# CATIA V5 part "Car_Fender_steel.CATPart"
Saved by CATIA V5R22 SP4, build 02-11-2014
Part number: Car_Fender
Material "ｽﾁｰﾙ": density 7860 kg/m3, Young's modulus 2e+11 Pa, Poisson ratio 0.266, thermal expansion 1.17e-05 1/K
Bounding box of the stored display mesh (mm): x -800 to 0, y -40 to 122.298, z 0 to 580
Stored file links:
  \\172.16.16.24\714_東北電子専門学校\2014年度\02_実施プロセス\catia_model_data\CAE_data\Car_modify\Car_Fender_steel.CATPart
  C:\Program Files\Dassault Systemes\B22\win_b64\startup\materials\red_env_512x512.jpg
  C:\Program Files\Dassault Systemes\B22\win_b64\startup\materials\yellow_env_512x512.jpg

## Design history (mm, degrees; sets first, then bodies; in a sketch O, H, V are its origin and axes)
Set1
  Plane1: type Offset, RefPlane yz-plane, Offset 400, reversed
  Plane2 "平面.2": type Offset, RefPlane Plane1, Offset 400, reversed
Body1 (main body)
  Body2
    Sketch1 on yz-plane, origin (0, 0, 0), H (0, 1, 0), V (0, 0, 1)
      point P1 (40.1932, 0)
      point P2 (100, 50)
      line L1 (100, 50) -> (100, 0)
      point P3 (100, 0)
      line L2 (100, 0) -> (0, 0)
      line L3 (0, 0) -> (0, 450)
      line L4 (0, 450) -> (10, 450)
      point P5 (10, 450)
      spline S1 through (10, 450) (100, 50)
      point P6 (10, 450)
      point P7 (100, 50)
      length L3 = 450
      length L2 = 100
      length L1 = 50
      length L4 = 10
      coincidence: P3 H, P6 P5, P7 P2
      vertical: L1 V, L3 V
      horizontal: L2 H, L4 H
    Sketch2 on Plane1, origin (-400, 0, 0), H (0, 1, 0), V (0, 0, 1)
      point P1 (40.1932, 0)
      point P2 (100, 50)
      line L1 (100, 50) -> (100, 0)
      point P3 (100, 0)
      line L2 (100, 0) -> (0, 0)
      line L3 (0, 0) -> (0, 530)
      line L4 (0, 530) -> (10, 530)
      point P5 (10, 530)
      spline S1 through (10, 530) (100, 50)
      point P6 (10, 530)
      point P7 (100, 50)
      length L3 = 530
      length L2 = 100
      length L1 = 50
      length L4 = 10
      coincidence: P3 H, P6 P5, P7 P2
      vertical: L1 V, L3 V
      horizontal: L2 H, L4 H
    Sketch3 on Plane2, origin (-800, 0, 0), H (0, 1, 0), V (0, 0, 1)
      point P1 (40.1932, 0)
      point P2 (100, 50)
      line L1 (100, 50) -> (100, 0)
      point P3 (100, 0)
      line L2 (100, 0) -> (0, 0)
      line L3 (0, 0) -> (0, 580)
      line L4 (0, 580) -> (10, 580)
      point P5 (10, 580)
      spline S1 through (10, 580) (100, 50)
      point P6 (10, 580)
      point P7 (100, 50)
      length L3 = 580
      length L2 = 100
      length L1 = 50
      length L4 = 10
      coincidence: P3 H, P6 P5, P7 P2
      vertical: L1 V, L3 V
      horizontal: L2 H, L4 H
    Loft1: solid, Sections (Sketch1; Sketch2; Sketch3)
    Body3
      Sketch4 on zx-plane, origin (0, 0, 0), H (-1, 0, 0), V (0, 0, 1)
        line L1 (-46.4952, 240) -> (159.0779, 240)
        arc A1 centre (390, 110) radius 265 from (159.0779, 240) to (655, 109.9999) cw
        point P2 (390, 110)
        line L2 (655, 109.9999) -> (655, -30)
        line L3 (-37.8358, 626.6258) -> (859.9489, 626.6258)
        line L4 (859.9489, 626.6258) -> (850, -30)
        line L5 (850, -30) -> (655, -30)
        line L6 (-37.8358, 626.6258) -> (-46.4952, 240)
        radius A1 = 265
        distance P2 H = 110
        distance V P2 = 390
        distance H L1 = 240
        horizontal: L1 H, L3 H, L5 H
        tangency: L2 A1
        vertical: L2 V
      Pad1: profile Sketch4, direction (0, 1, 0), length 340, mirrored extent
    Intersect1: tool Body3
    Sketch5 on Plane2, origin (-800, 0, 0), H (0, 1, 0), V (0, 0, 1)
      line L1 (0, 580) -> (0, 545)
      line L2 (-5, 540) -> (-40, 540)
      point P2 (-40, 540)
      reference projected line E1 (10, 580) -> (0, 580) from edge [face of Loft1 | face of Loft1]
      reference intersected line E2 (0, 0) -> (0, 580) from face of Loft1
      arc A1 centre (-5, 545) radius 5 from (-5, 540) to (0, 545) ccw
      line L3 (-5, 537) -> (-40, 537)
      arc A2 centre (-5, 545) radius 8 from (-5, 537) to (3, 545) ccw
      line L4 (3, 580) -> (3, 545)
      line L5 (-40, 537) -> (-40, 540)
      line L6 (3, 580) -> (0, 580)
      reference projected line E3 (10, 580) -> (0, 580) from edge [face of Loft1 | face of Loft1]
      distance E1 L2 = 40
      radius A1 = 5
      distance L1 P2 = 40
      length L5 = 3
      length L6 = 3
      radius A2 = 8
      vertical: L1 V, L4 V, L5 V
      horizontal: L2 H, L6 H, L3 H
      coincidence: L1 E2, L6 E3
      tangency: A1 L2, A1 L1, L4 A2, A2 L3
    Shell1: ExtOffset 0, Face (face of Loft1; face of Loft1; face of Pad1 from Sketch4.A1; face of Loft1; face of Pad1 from Sketch4.L1; face of Loft1), IntOffset 3
    Rib1: profile Sketch5, centre curve edge [face of Loft1 | face of Loft1]
    Sketch6 on Plane2, origin (-800, 0, 0), H (0, 1, 0), V (0, 0, 1)
      projected line E1 (97, 0) -> (97, 50) from edge [face of Shell1 | face of Rib1]
      projected curve E2 from edge [face of Shell1 | face of Rib1]
      projected line E3 (10, 576.9862) -> (3, 576.9862) from edge [face of Shell1 | face of Rib1]
      point P6 (3, 576.9862)
      projected line E4 (3, 576.9862) -> (3, 545) from edge [face of Rib1 | face of Rib1]
      projected line E5 (3, 576.9862) -> (3, 399.233) from edge [face of Rib1 | face of Rib1]
      point P7 (3, 576.9862)
      line L1 (97, 0) -> (37, 0)
      line L2 (37, 0) -> (17.9077, 155.4943)
      arc A1 centre (2003, 399.233) radius 2000 from (17.9077, 155.4943) to (3, 399.233) cw
      angle L1 L2 = 97
      length L1 = 60
      radius A1 = 2000
      horizontal: L1 H
      coincidence: P6 P7
      tangency: A1 L2, A1 E4
    Pad2: profile Sketch6, direction (1, 0, 0), length 10, opposite side length -7
    Sketch7 on yz-plane, origin (0, 0, 0), H (0, 1, 0), V (0, 0, 1)
      projected curve E1 from edge [face of Loft1 | face of Shell1]
      projected curve E2 from edge [face of Loft1 | face of Shell1]
      line L1 (103.8705, 240) -> (92.1161, 240)
      line L2 (89.1161, 237) -> (89.1161, 160)
      line L3 (89.1161, 160) -> (86.1161, 160)
      line L4 (86.1161, 160) -> (86.1161, 237)
      line L5 (92.1161, 243) -> (100.927, 243)
      offset curve E3 from edge [face of Loft1 | face of Shell1]
      offset curve E4 from edge [face of Loft1 | face of Shell1]
      line L6 (101.1109, 260) -> (104.111, 260)
      reference projected line E5 (0, 240) -> (106.8716, 240) from edge [face of Pad1 from Sketch4.L1 | face of Loft1]
      arc A1 centre (92.1161, 237) radius 3 from (89.1161, 237) to (92.1161, 240) cw
      arc A2 centre (92.1161, 237) radius 6 from (86.1161, 237) to (92.1161, 243) cw
      length L3 = 3
      length L6 = 3
      distance L5 L1 = 3
      distance E5 L3 = 80
      distance L2 E1 = 15
      radius A1 = 3
      radius A2 = 6
      horizontal: L1 H, L3 H, L5 H, L6 H
      vertical: L2 V, L4 V
      tangency: A1 L2, A1 L1, A2 L4, A2 L5
    Rib2: profile Sketch7, centre curve edge [face of Pad1 from Sketch4.L1 | face of Shell1]
    Body4
      Sketch8 on zx-plane, origin (0, 0, 0), H (-1, 0, 0), V (0, 0, 1)
        point P1 (0, 300)
        line L1 (0, 300) -> (127.0171, 520)
        line L2 (127.0171, 520) -> (-100, 520)
        line L3 (-100, 520) -> (-100, 300)
        line L4 (-100, 300) -> (0, 300)
        angle L1 L4 = 120
        distance L4 H = 300
        coincidence: P1 V
        horizontal: L2 H, L4 H
        vertical: L3 V
      Pad3: profile Sketch8, direction (0, 1, 0), length 218, mirrored extent
    Remove1: tool Body4
    Sketch9 on xy-plane, origin (0, 0, 0), H (1, 0, 0), V (0, 1, 0)
      line L1 (-730, -50) -> (-730, -25)
      arc A1 centre (-725, -25) radius 5 from (-730, -25) to (-720, -25) cw
      point P3 (-725, -25)
      line L2 (-720, -25) -> (-720, -50)
      line L3 (-720, -50) -> (-730, -50)
      reference projected line E1 (-800, -40) -> (-800, -5) from edge [face of Rib1 | face of Rib1]
      reference projected line E2 (-5.7993, -40) -> (-800, -40) from edge [face of Rib1 | face of Rib1]
      distance E1 L1 = 70
      length L3 = 10
      distance P3 E2 = 15
      radius A1 = 5
      vertical: L1 V
      tangency: A1 L1, L2 A1
      horizontal: L3 H
    Pocket1: profile Sketch9, direction (0, 0, 1), length 657
    RectPattern1: of Pocket1, direction 1 instances 3, spacing 270, along X axis
    Sketch10 on {plane type Tangent, Support face of Rib2, RefPoint {point type OnSurface, Support face of Rib2, RefPoint {point stored without definition}, Length 0, Direction (0, 0, -1000)}}, origin (-34.1531, 89.7232, 188.2636), H (0.9999, -0.0168, 0), V (0, 0, 1)
      point P1 (-15.8415, 1.7364)
      reference projected line E1 (-124.8302, -28.2636) -> (34.1585, -28.2636) from edge [face of Rib2 | face of Rib2]
      reference projected line E2 (34.1585, -28.2636) -> (34.1585, 48.7364) from edge [face of Rib2 | face of Rib2]
      distance P1 E1 = 30
      distance P1 E2 = 50
    Hole1: placed by Sketch10, at (-49.9925, 89.9835, 190) direction (-0.016, -0.9999, 0), diameter 15, through (limit type 3)
    Fillet1: radius 10, on edge [face of Rib1 | face of Rib1]; edge [face of Rib1 | face of Pad3 from Sketch8.L1]
    Chamfer1: length 70, angle 35, on edge [face of Rib2 | face of Rib2]
    Fillet2: radius 5, on edge [face of Rib2 | face of Rib2]; edge [face of Chamfer1 | face of Rib2]; edge [face of Rib2 | face of Chamfer1]
    Fillet3: radius 10, on edge [face of Pad1 from Sketch4.L2 | face of Pad2]
  Add1: tool Body2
